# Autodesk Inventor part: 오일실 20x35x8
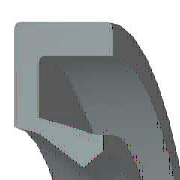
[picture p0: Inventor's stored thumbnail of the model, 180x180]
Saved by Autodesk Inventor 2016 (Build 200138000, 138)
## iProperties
IsCustomPart: 1
Created: 2012-02
Part Number: 오일실 20x35x8
Material: 고무
Description: 오일 실 - 비스프링, 조립 GA
Document SubType Name: Modeling
Standard: JIS B 2402
Designer: mdu-01
Standards Organization: JIS
Language: ko-KR
Size Designation: 20 35 8 A
Categories: <MemberInstance><Categories><Category DisplayName="샤프트 부품" InternalName="7f7aeb1f-a693-4053-b835-cee3144e0d98" Mnemonic="SHFT"><Category DisplayName="실링" Intern
Density: 0.93 g/cm^3
Appearance: Rubber-Black
Author: mdu-01
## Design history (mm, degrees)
body "Solid1"
revolve "회전1" stored, may be unused: angle "d27" = 360 deg
fillet "모깎기1" dims "d28" = 0.4 (= 0.05 x b)
sketch "스케치2"
  geometry: L1 (12.464, -6)-(13.214, -8); L2 (11.464, -5.5)-(12.464, -6); L3 (10, -2.2)-(11.464, -5.5); L4 (11.154, -1.2)-(10, -2.2); L5 (14.5, -7)-(11.154, -1.2); L6 (14.5, -0.4)-(14.5, -7); L7 (16, -0.4)-(14.5, -0.4); L8 (16, 0)-(16, -0.4); L9 (17.5, 0)-(16, 0); L10 (17.5, -8)-(17.5, 0); L11 (13.214, -8)-(17.5, -8); L12 (0, -9.6)-(0, 1.6) reference; L13 (28, 0)-(14, 0) reference
  constraints: 22 end point, 3 horizontal, 3 vertical
  dimensions: "d2" = 8 distance of L10.start L9.start (= b); "d4" = 1.5 distance of L9.start L8.start (= 0.1 x dd - 0.1 x Diam); "d6" = 0.4 distance of L8.start L7.start (= 0.05 x b); "d8" = 1.15385 horizontal distance of L4.start L3.start (= 0.0769231 x dd - 0.0769231 x Diam); "d10" = 1 vertical distance of L5.start L10.start (= 0.125 x b); "d12" = 1.5 distance of L7.start L6.start (= 0.1 x dd - 0.1 x Diam); "d14" = 0.8 vertical distance of L4.start L6.start (= 0.1 x b); "d16" = 4.28571 distance of L1.end L10.start (= 0.285714 x dd - 0.285714 x Diam); "d18" = 0.75 horizontal distance of L1.start L1.end (= 0.05 x dd - 0.05 x Diam); "d20" = 1 vertical distance of L4.start L3.start (= 0.125 x b); "d22" = 2 vertical distance of L1.start L1.end (= 0.25 x b); "d24" = 1 horizontal distance of L2.start L1.start (= 0.0666667 x dd - 0.0666667 x Diam); "d26" = 0.5 vertical distance of L2.start L1.start (= 0.0625 x b); "d29" = 0 distance between parallel lines of L13 L9; "d30" = 10 distance from line of L3.start L12 (= 0.5 x Diam); "d31" = 17.5 distance between parallel lines of L12 L10 (= 0.5 x dd)
other parameters: "dd" = 35 [user parameter; used in 7 equation terms], "b" = 8 [user parameter; used in 8 equation terms], "d1" = 8 (derived), "d3" = 2 (derived), "d5" = 0.4 (derived), "d7" = 1.53846 (derived), "d9" = 1 (derived), "d11" = 2 (derived), "d13" = 0.8 (derived), "d15" = 5.71429 (derived), "d17" = 1 (derived), "d19" = 1 (derived), "d21" = 2 (derived), "d23" = 1.33333 (derived), "d25" = 0.5 (derived), "d32" = 0
